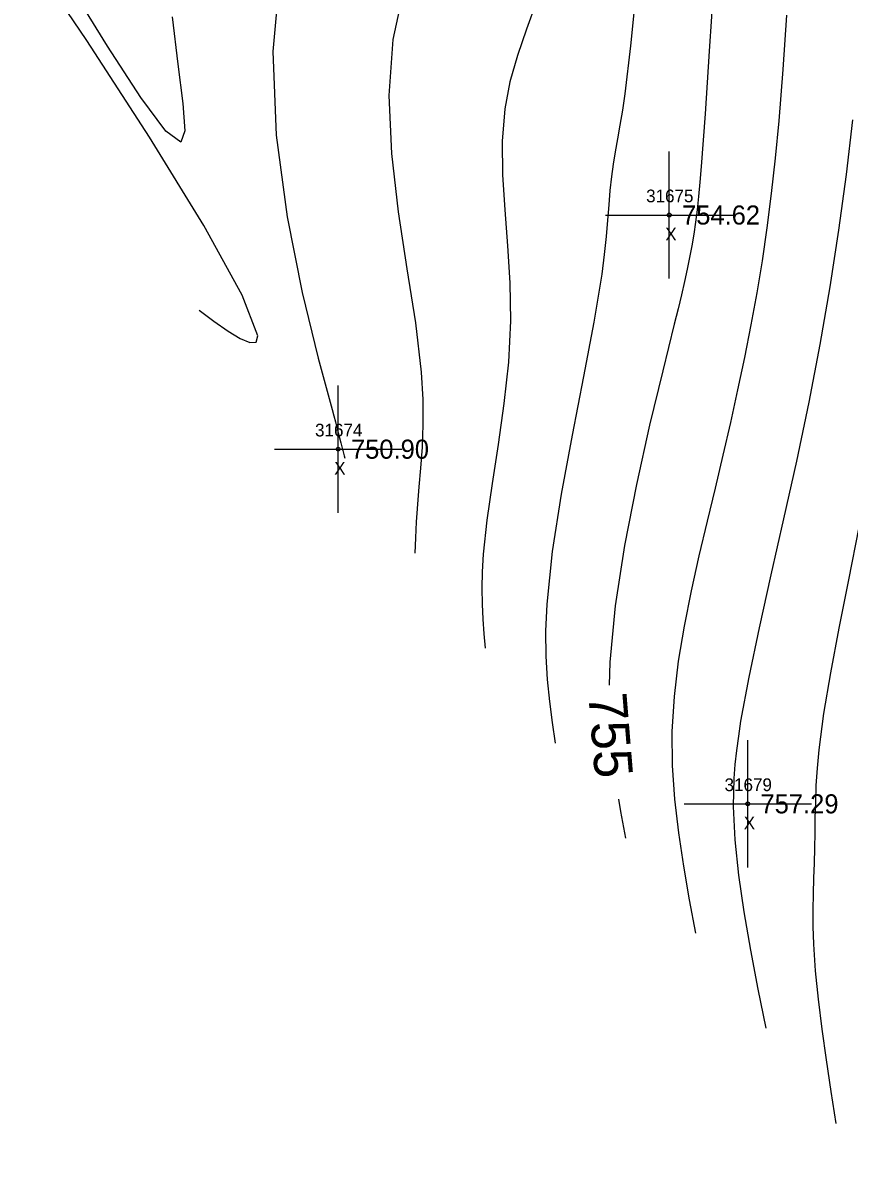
# Model space of a CAD drawing. Extents: x 1376587 to 1378239, y 1000335 to 1003031.
# Drawn here: x 1377869.7 to 1377934.6, y 1000518.5 to 1000608.4 of the extents above; entities that cross this region are included whole.
import ezdxf

# ---------------------------------------------------------------- set-up
doc = ezdxf.new("R2010")
doc.units = 0
for name, color, linetype in [('RD_DTM_BkLn1', 7, 'Continuous'), ('RD_DTM_Major1', 7, 'Continuous'), ('RD_DTM_Major1_Lbl', 7, 'Continuous'), ('RD_DTM_Minor1', 7, 'Continuous'), ('RD_EX_Misc', 7, 'Continuous'), ('RD_EX_Misc_txCode', 7, 'Continuous'), ('RD_EX_Road', 7, 'Continuous'), ('RD_EX_TX_Misc_ELEV', 7, 'Continuous'), ('RD_SMD_Locator', 7, 'Continuous')]:
    doc.layers.add(name, color=color, linetype=linetype)

msp = doc.modelspace()

# ---------------------------------------------------------------- linework, layer by layer
at = {"layer": 'RD_DTM_BkLn1'}
msp.add_spline([(1378169.212, 1000387.103), (1378131.506, 1000434.744), (1378095.477, 1000481.988), (1378063.033, 1000526.867), (1378030.177, 1000574.233), (1377998.011, 1000622.539), (1377965.721, 1000673.201), (1377936, 1000721.493), (1377904.113, 1000773.429), (1377890.868, 1000795.129)], degree=3, dxfattribs=at)
at = {"layer": 'RD_DTM_Major1'}
for points in [[(1377881.411, 1000608.862), (1377881.848, 1000605.122), (1377882.241, 1000602.029), (1377882.384, 1000599.888), (1377882.072, 1000599.002), (1377880.9, 1000599.852), (1377878.936, 1000602.505), (1377876.33, 1000606.55), (1377873.231, 1000611.578)], [(1377923.965, 1000611.638), (1377923.602, 1000606.163), (1377923.283, 1000601.228), (1377922.982, 1000597.079), (1377922.876, 1000595.844), (1377922.766, 1000594.716), (1377922.65, 1000593.674), (1377922.525, 1000592.699), (1377922.389, 1000591.768), (1377922.238, 1000590.862), (1377922.067, 1000589.945), (1377921.877, 1000589.011), (1377921.663, 1000588.04), (1377921.424, 1000587.011), (1377921.158, 1000585.904), (1377920.862, 1000584.698), (1377919.951, 1000581.019), (1377918.924, 1000576.743), (1377917.888, 1000572.093), (1377916.95, 1000567.291), (1377916.216, 1000562.561), (1377915.794, 1000558.124), (1377915.748, 1000556.324)], [(1377916.479, 1000547.368), (1377916.641, 1000546.375), (1377917.017, 1000544.28)]]:
    msp.add_lwpolyline(points, dxfattribs=at)
at = {"layer": 'RD_DTM_Minor1'}
for points in [[(1377883.515, 1000585.796), (1377884.686, 1000584.93), (1377885.788, 1000584.154), (1377886.752, 1000583.56), (1377887.508, 1000583.239), (1377887.988, 1000583.281), (1377888.121, 1000583.779), (1377886.892, 1000586.977), (1377883.875, 1000592.449), (1377879.628, 1000599.387), (1377874.706, 1000606.983), (1377869.666, 1000614.432)], [(1377889.883, 1000612.498), (1377889.311, 1000606.115), (1377889.578, 1000599.554), (1377890.43, 1000593.137), (1377891.614, 1000587.188), (1377892.877, 1000582.03), (1377893.964, 1000577.985), (1377894.099, 1000577.483), (1377894.226, 1000577.011), (1377894.344, 1000576.567), (1377894.455, 1000576.147), (1377894.559, 1000575.75), (1377894.658, 1000575.371), (1377894.712, 1000575.16), (1377894.765, 1000574.955), (1377894.818, 1000574.752), (1377894.869, 1000574.552), (1377894.92, 1000574.354), (1377894.971, 1000574.156)], [(1377899.518, 1000610.707), (1377898.737, 1000607.066), (1377898.429, 1000602.662), (1377898.63, 1000598.102), (1377899.162, 1000593.518), (1377899.848, 1000589.04), (1377900.512, 1000584.798), (1377900.977, 1000580.925), (1377901.099, 1000578.781), (1377901.11, 1000576.816), (1377901.042, 1000575.019), (1377900.925, 1000573.383), (1377900.791, 1000571.898), (1377900.669, 1000570.554), (1377900.616, 1000569.843), (1377900.575, 1000569.168), (1377900.543, 1000568.522), (1377900.519, 1000567.899), (1377900.499, 1000567.289), (1377900.482, 1000566.687)], [(1377917.861, 1000611.036), (1377917.43, 1000606.571), (1377916.979, 1000602.789), (1377916.787, 1000601.506), (1377916.592, 1000600.337), (1377916.403, 1000599.258), (1377916.224, 1000598.243), (1377916.063, 1000597.27), (1377915.926, 1000596.312), (1377915.804, 1000595.209), (1377915.703, 1000594.069), (1377915.607, 1000592.867), (1377915.496, 1000591.577), (1377915.352, 1000590.175), (1377915.157, 1000588.634), (1377914.537, 1000584.86), (1377913.721, 1000580.567), (1377912.825, 1000575.98), (1377911.967, 1000571.321), (1377911.265, 1000566.815), (1377910.836, 1000562.686), (1377910.751, 1000560.561), (1377910.774, 1000558.602), (1377910.882, 1000556.773), (1377911.054, 1000555.044), (1377911.269, 1000553.38), (1377911.506, 1000551.749)], [(1377910.014, 1000609.984), (1377909.241, 1000607.885), (1377908.529, 1000605.817), (1377907.938, 1000603.738), (1377907.53, 1000601.608), (1377907.334, 1000599.07), (1377907.367, 1000596.424), (1377907.538, 1000593.679), (1377907.758, 1000590.848), (1377907.937, 1000587.94), (1377907.985, 1000584.967), (1377907.818, 1000581.708), (1377907.473, 1000578.447), (1377907.026, 1000575.247), (1377906.554, 1000572.169), (1377906.136, 1000569.275), (1377905.848, 1000566.626), (1377905.768, 1000565.237), (1377905.745, 1000563.932), (1377905.767, 1000562.695), (1377905.824, 1000561.508), (1377905.903, 1000560.355), (1377905.994, 1000559.218)], [(1377929.684, 1000608.974), (1377929.392, 1000604.724), (1377929.073, 1000600.667), (1377928.795, 1000597.742), (1377928.484, 1000594.955), (1377928.138, 1000592.278), (1377927.757, 1000589.684), (1377927.339, 1000587.145), (1377926.882, 1000584.634), (1377926.378, 1000582.084), (1377925.839, 1000579.531), (1377925.27, 1000576.969), (1377924.678, 1000574.396), (1377924.068, 1000571.806), (1377923.445, 1000569.196), (1377922.799, 1000566.47), (1377922.181, 1000563.724), (1377921.625, 1000560.965), (1377921.165, 1000558.199), (1377920.837, 1000555.433), (1377920.674, 1000552.673), (1377920.697, 1000550.011), (1377920.875, 1000547.359), (1377921.179, 1000544.715), (1377921.577, 1000542.077), (1377922.037, 1000539.443), (1377922.529, 1000536.811)], [(1377934.865, 1000600.747), (1377934.37, 1000596.466), (1377933.777, 1000592.082), (1377933.088, 1000587.62), (1377932.305, 1000583.103), (1377931.431, 1000578.555), (1377930.459, 1000573.933), (1377929.448, 1000569.383), (1377928.451, 1000564.984), (1377927.521, 1000560.817), (1377926.711, 1000556.958), (1377926.075, 1000553.488), (1377925.893, 1000552.309), (1377925.743, 1000551.178), (1377925.627, 1000550.077), (1377925.547, 1000548.99), (1377925.503, 1000547.9), (1377925.497, 1000546.789), (1377925.619, 1000544.169), (1377925.906, 1000541.393), (1377926.325, 1000538.49), (1377926.842, 1000535.493), (1377927.425, 1000532.433), (1377928.041, 1000529.342)], [(1377935.361, 1000568.724), (1377934.547, 1000564.603), (1377933.791, 1000560.785), (1377933.127, 1000557.278), (1377932.589, 1000554.094), (1377932.211, 1000551.243), (1377932.079, 1000549.788), (1377931.994, 1000548.424), (1377931.945, 1000547.132), (1377931.917, 1000545.895), (1377931.899, 1000544.696), (1377931.877, 1000543.515), (1377931.842, 1000542.33), (1377931.801, 1000541.133), (1377931.765, 1000539.911), (1377931.744, 1000538.652), (1377931.75, 1000537.343), (1377931.793, 1000535.969), (1377931.933, 1000533.863), (1377932.157, 1000531.625), (1377932.448, 1000529.28), (1377932.788, 1000526.855), (1377933.162, 1000524.377), (1377933.552, 1000521.873)]]:
    msp.add_lwpolyline(points, dxfattribs=at)
at = {"layer": 'RD_EX_Misc'}
for p, q in [((1377920.465, 1000588.272), (1377920.465, 1000598.272)), ((1377915.465, 1000593.272), (1377925.465, 1000593.272)), ((1377894.447, 1000569.866), (1377894.447, 1000579.866)), ((1377889.447, 1000574.866), (1377899.447, 1000574.866)), ((1377926.631, 1000541.988), (1377926.631, 1000551.988)), ((1377921.631, 1000546.988), (1377931.631, 1000546.988))]:
    msp.add_line(p, q, dxfattribs=at)
at = {"layer": 'RD_EX_Road'}
for points in [[(1378177.15, 1000392.854), (1378139.733, 1000441.521), (1378104.671, 1000487.69), (1378071.786, 1000533.085), (1378038.454, 1000579.804), (1378007.554, 1000627.96), (1377974.27, 1000678.859), (1377944.465, 1000727.117), (1377913.028, 1000778.581), (1377899.668, 1000800.294)], [(1378161.362, 1000381.162), (1378123.914, 1000428.538), (1378087.578, 1000476.324), (1378055.075, 1000520.944), (1378021.673, 1000568.713), (1377989.952, 1000617.081), (1377957.327, 1000668.378), (1377927.534, 1000716.552), (1377895.409, 1000768.824), (1377883.752, 1000788.501)]]:
    msp.add_spline(points, degree=3, dxfattribs=at)
at = {"layer": 'RD_SMD_Locator'}
for centre in [(1377920.465, 1000593.272), (1377894.447, 1000574.866), (1377926.631, 1000546.988)]:
    msp.add_circle(centre, 0.15, dxfattribs=at)

# ---------------------------------------------------------------- texts
at = {"layer": 'RD_DTM_Major1_Lbl'}
msp.add_text('755', height=3, rotation=274.66744, dxfattribs=at).set_placement((1377914.098, 1000555.593))
at = {"layer": 'RD_EX_Misc_txCode'}
for s, p in [('31675', (1377918.646, 1000594.272)), ('X', (1377920.15, 1000591.272)), ('31674', (1377892.628, 1000575.866)), ('X', (1377894.132, 1000572.866)), ('31679', (1377924.812, 1000547.988)), ('X', (1377926.316, 1000544.988))]:
    msp.add_text(s, height=1, dxfattribs=at).set_placement(p)
at = {"layer": 'RD_EX_TX_Misc_ELEV'}
for s, p in [('754.62', (1377921.465, 1000592.522)), ('750.90', (1377895.447, 1000574.116)), ('757.29', (1377927.631, 1000546.238))]:
    msp.add_text(s, height=1.5, dxfattribs=at).set_placement(p)

doc.saveas('drawing.dxf')
